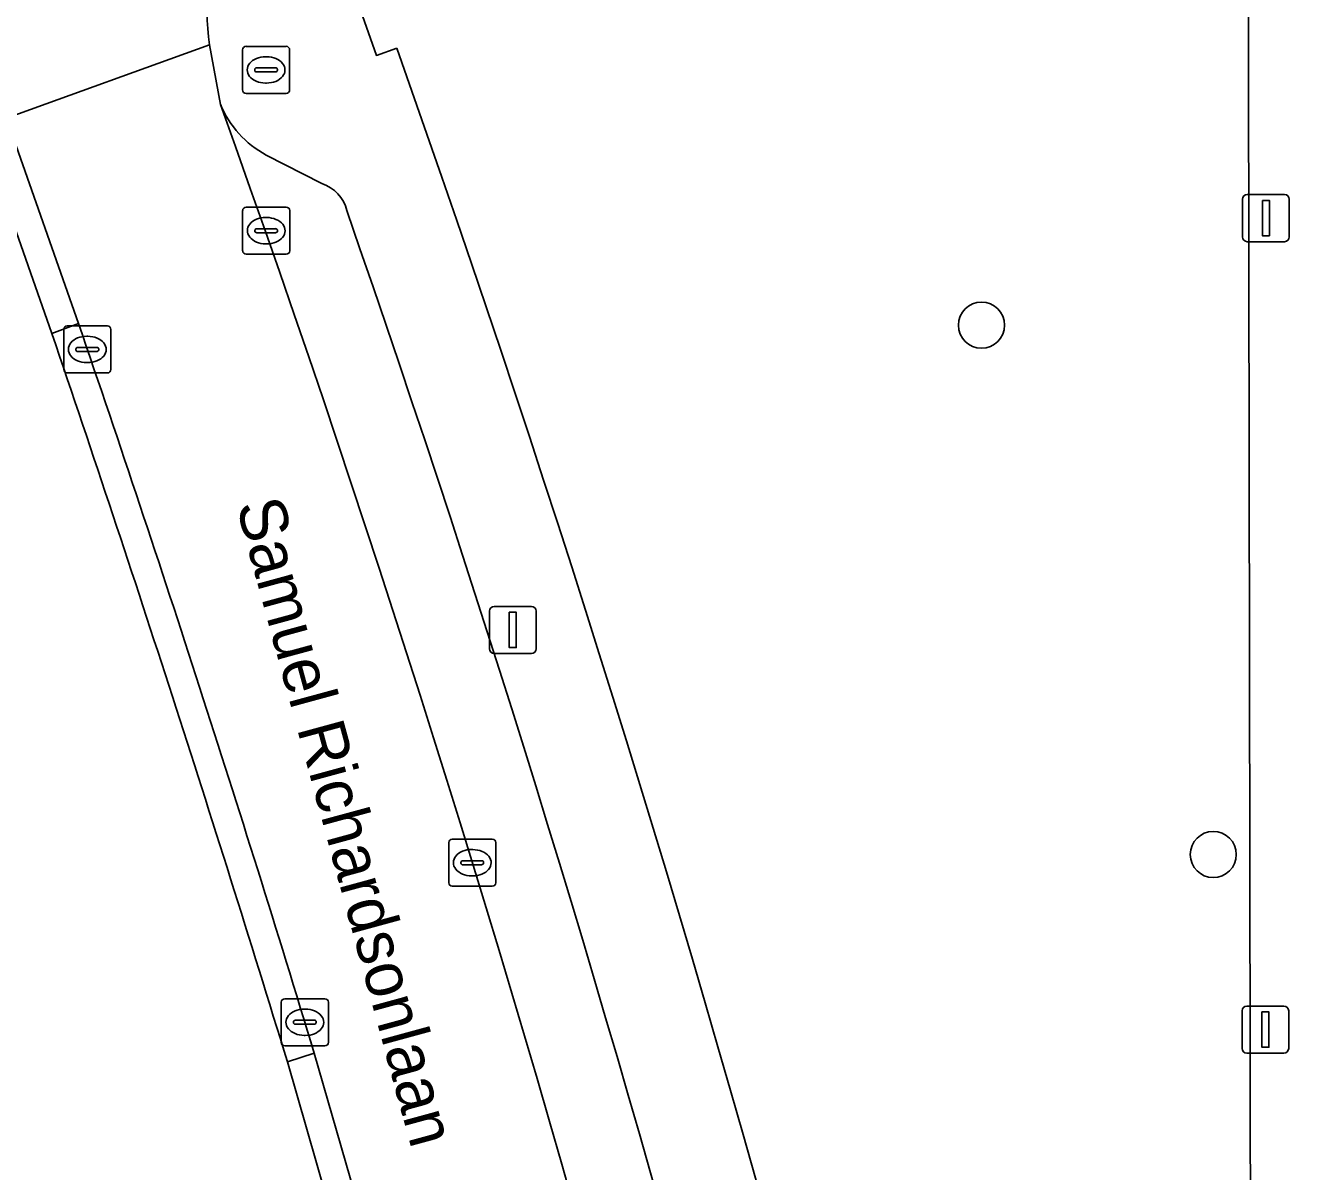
# Model space of a CAD drawing. Extents: x 160455 to 162082, y 388339 to 389736.
# Drawn here: x 160861.12 to 160888.53, y 388583.49 to 388607.82 of the extents above; entities that cross this region are included whole.
import ezdxf

# ---------------------------------------------------------------- set-up
doc = ezdxf.new("R2010")
doc.units = 0
for name, color, linetype in [('IMGEO_Boom', 7, 'Continuous'), ('IMGEO_Brandkraan', 7, 'Continuous'), ('IMGEO_Erf', 7, 'Continuous'), ('IMGEO_Groenvoorziening', 7, 'Continuous'), ('IMGEO_Kolk', 7, 'Continuous'), ('IMGEO_Lichtmast', 7, 'Continuous'), ('IMGEO_Openbare_ruimte_label', 7, 'Continuous'), ('IMGEO_Parkeervlak_open', 7, 'Continuous'), ('IMGEO_Rijbaan_lokaal_open', 7, 'Continuous'), ('IMGEO_Voetpad_open', 7, 'Continuous')]:
    doc.layers.add(name, color=color, linetype=linetype)

msp = doc.modelspace()

# ---------------------------------------------------------------- linework, layer by layer
at = {"layer": 'IMGEO_Boom'}
for centre in [(160881.421, 388601.46), (160886.345, 388590.216)]:
    msp.add_circle(centre, 0.489, dxfattribs=at)
at = {"layer": 'IMGEO_Brandkraan'}
for p, q in [((160865.722, 388606.457), (160865.722, 388607.309)), ((160865.797, 388607.383), (160866.649, 388607.383)), ((160866.723, 388607.309), (160866.723, 388606.457)), ((160866.21, 388607.163), (160866.235, 388607.163)), ((160865.981, 388606.877), (160865.981, 388606.889)), ((160866.419, 388606.84), (160866.021, 388606.84)), ((160866.024, 388606.926), (160866.422, 388606.926)), ((160866.465, 388606.889), (160866.465, 388606.877)), ((160866.233, 388606.603), (160866.208, 388606.603)), ((160866.649, 388606.383), (160865.797, 388606.383))]:
    msp.add_line(p, q, dxfattribs=at)
for points in [[(160865.722, 388606.457), (160865.722, 388607.309)], [(160865.797, 388607.383), (160866.649, 388607.383)], [(160866.723, 388607.309), (160866.723, 388606.457)], [(160866.649, 388606.383), (160865.797, 388606.383)]]:
    msp.add_lwpolyline(points, dxfattribs=at)
for centre, radius, start, end in [((160865.799, 388607.307), 0.0765, 91.552, 178.448), ((160865.799, 388607.307), 0.0765, 91.552, 178.448), ((160866.647, 388607.307), 0.0765, 1.552, 88.448), ((160866.647, 388607.307), 0.0765, 1.552, 88.448), ((160866.021, 388606.886), 0.0403, 85.8775, 175.7526), ((160866.018, 388606.876), 0.0366, 178.938, 274.7102), ((160866.422, 388606.883), 0.043, 264.8664, 352.4533), ((160866.426, 388606.888), 0.0386, 1.7309, 96.639), ((160865.799, 388606.459), 0.0765, 181.552, 268.448), ((160865.799, 388606.459), 0.0765, 181.552, 268.448), ((160866.647, 388606.459), 0.0765, 271.552, 358.448), ((160866.647, 388606.459), 0.0765, 271.552, 358.448)]:
    msp.add_arc(centre, radius, start, end, dxfattribs=at)
for centre, major_axis, ratio, start_param, end_param in [((160866.209, 388606.883), (-0.387, 0.002), 0.722429, 4.712389, 7.853982), ((160866.234, 388606.883), (-0.39, 0.002), 0.717154, 1.570796, 4.712389)]:
    msp.add_ellipse(centre, major_axis=major_axis, ratio=ratio, start_param=start_param, end_param=end_param, dxfattribs=at)
at = {"layer": 'IMGEO_Erf'}
for points in [[(160861.672, 388601.285), (160860.206, 388605.457)], [(160868.112, 388580.808), (160866.675, 388585.815)]]:
    msp.add_lwpolyline(points, dxfattribs=at)
msp.add_arc((160370.776, 388433.985), 518.621, 17.02306, 18.81937, dxfattribs=at)
at = {"layer": 'IMGEO_Groenvoorziening'}
for points in [[(160884.845, 388547.466), (160887.189, 388547.484), (160887.078, 388615.554)], [(160866.752, 388612.348), (160868.566, 388607.191), (160868.998, 388607.347)]]:
    msp.add_lwpolyline(points, dxfattribs=at)
msp.add_arc((160512.993, 388481.096), 377.728, 10.11988, 19.52619, dxfattribs=at)
at = {"layer": 'IMGEO_Kolk'}
for p, q in [((160865.725, 388603.041), (160865.725, 388603.893)), ((160865.8, 388603.967), (160866.652, 388603.967)), ((160866.213, 388603.747), (160866.238, 388603.747)), ((160866.726, 388603.893), (160866.726, 388603.041)), ((160865.984, 388603.461), (160865.984, 388603.473)), ((160866.027, 388603.51), (160866.425, 388603.51)), ((160866.468, 388603.473), (160866.468, 388603.461)), ((160866.422, 388603.424), (160866.024, 388603.424)), ((160866.236, 388603.187), (160866.211, 388603.187)), ((160866.652, 388602.967), (160865.8, 388602.967)), ((160861.924, 388600.519), (160861.924, 388601.371)), ((160861.999, 388601.445), (160862.851, 388601.445)), ((160862.925, 388601.371), (160862.925, 388600.519)), ((160862.226, 388600.988), (160862.624, 388600.988)), ((160862.412, 388601.225), (160862.437, 388601.225)), ((160862.183, 388600.939), (160862.183, 388600.951)), ((160862.621, 388600.902), (160862.223, 388600.902)), ((160862.667, 388600.951), (160862.667, 388600.939)), ((160862.851, 388600.445), (160861.999, 388600.445)), ((160862.435, 388600.665), (160862.41, 388600.665)), ((160870.102, 388589.616), (160870.102, 388590.468)), ((160870.177, 388590.542), (160871.029, 388590.542)), ((160870.59, 388590.322), (160870.615, 388590.322)), ((160871.103, 388590.468), (160871.103, 388589.616)), ((160870.361, 388590.036), (160870.361, 388590.048)), ((160870.404, 388590.085), (160870.802, 388590.085)), ((160870.845, 388590.048), (160870.845, 388590.036)), ((160870.799, 388589.999), (160870.401, 388589.999)), ((160870.613, 388589.762), (160870.588, 388589.762)), ((160871.029, 388589.542), (160870.177, 388589.542)), ((160866.545, 388586.227), (160866.545, 388587.079)), ((160866.62, 388587.153), (160867.472, 388587.153)), ((160867.546, 388587.079), (160867.546, 388586.227)), ((160867.033, 388586.933), (160867.058, 388586.933)), ((160866.804, 388586.647), (160866.804, 388586.659)), ((160867.242, 388586.61), (160866.844, 388586.61)), ((160866.847, 388586.696), (160867.245, 388586.696)), ((160867.288, 388586.659), (160867.288, 388586.647)), ((160867.056, 388586.373), (160867.031, 388586.373)), ((160867.472, 388586.153), (160866.62, 388586.153))]:
    msp.add_line(p, q, dxfattribs=at)
for points in [[(160865.725, 388603.041), (160865.725, 388603.893)], [(160865.8, 388603.967), (160866.652, 388603.967)], [(160866.726, 388603.893), (160866.726, 388603.041)], [(160866.652, 388602.967), (160865.8, 388602.967)], [(160861.924, 388600.519), (160861.924, 388601.371)], [(160861.999, 388601.445), (160862.851, 388601.445)], [(160862.925, 388601.371), (160862.925, 388600.519)], [(160862.851, 388600.445), (160861.999, 388600.445)], [(160870.102, 388589.616), (160870.102, 388590.468)], [(160870.177, 388590.542), (160871.029, 388590.542)], [(160871.103, 388590.468), (160871.103, 388589.616)], [(160871.029, 388589.542), (160870.177, 388589.542)], [(160866.545, 388586.227), (160866.545, 388587.079)], [(160866.62, 388587.153), (160867.472, 388587.153)], [(160867.546, 388587.079), (160867.546, 388586.227)], [(160867.472, 388586.153), (160866.62, 388586.153)]]:
    msp.add_lwpolyline(points, dxfattribs=at)
for centre, radius, start, end in [((160865.802, 388603.891), 0.0765, 91.552, 178.448), ((160865.802, 388603.891), 0.0765, 91.552, 178.448), ((160866.65, 388603.891), 0.0765, 1.552, 88.448), ((160866.65, 388603.891), 0.0765, 1.552, 88.448), ((160866.024, 388603.47), 0.0403, 85.8775, 175.7526), ((160866.021, 388603.46), 0.0366, 178.938, 274.7102), ((160866.425, 388603.467), 0.043, 264.8664, 352.4533), ((160866.429, 388603.472), 0.0386, 1.7309, 96.639), ((160865.802, 388603.043), 0.0765, 181.552, 268.448), ((160865.802, 388603.043), 0.0765, 181.552, 268.448), ((160866.65, 388603.043), 0.0765, 271.552, 358.448), ((160866.65, 388603.043), 0.0765, 271.552, 358.448), ((160862.001, 388601.369), 0.0765, 91.552, 178.448), ((160862.001, 388601.369), 0.0765, 91.552, 178.448), ((160862.849, 388601.369), 0.0765, 1.552, 88.448), ((160862.849, 388601.369), 0.0765, 1.552, 88.448), ((160862.223, 388600.948), 0.0403, 85.8775, 175.7526), ((160862.628, 388600.95), 0.0386, 1.7309, 96.639), ((160862.22, 388600.938), 0.0366, 178.938, 274.7102), ((160862.624, 388600.945), 0.043, 264.8664, 352.4533), ((160862.001, 388600.521), 0.0765, 181.552, 268.448), ((160862.001, 388600.521), 0.0765, 181.552, 268.448), ((160862.849, 388600.521), 0.0765, 271.552, 358.448), ((160862.849, 388600.521), 0.0765, 271.552, 358.448), ((160870.179, 388590.466), 0.0765, 91.552, 178.448), ((160870.179, 388590.466), 0.0765, 91.552, 178.448), ((160871.027, 388590.466), 0.0765, 1.552, 88.448), ((160871.027, 388590.466), 0.0765, 1.552, 88.448), ((160870.401, 388590.045), 0.0403, 85.8775, 175.7526), ((160870.398, 388590.035), 0.0366, 178.938, 274.7102), ((160870.802, 388590.042), 0.043, 264.8664, 352.4533), ((160870.806, 388590.047), 0.0386, 1.7309, 96.639), ((160870.179, 388589.618), 0.0765, 181.552, 268.448), ((160870.179, 388589.618), 0.0765, 181.552, 268.448), ((160871.027, 388589.618), 0.0765, 271.552, 358.448), ((160871.027, 388589.618), 0.0765, 271.552, 358.448), ((160866.622, 388587.077), 0.0765, 91.552, 178.448), ((160866.622, 388587.077), 0.0765, 91.552, 178.448), ((160867.47, 388587.077), 0.0765, 1.552, 88.448), ((160867.47, 388587.077), 0.0765, 1.552, 88.448), ((160866.844, 388586.656), 0.0403, 85.8775, 175.7526), ((160866.841, 388586.646), 0.0366, 178.938, 274.7102), ((160867.245, 388586.653), 0.043, 264.8664, 352.4533), ((160867.249, 388586.658), 0.0386, 1.7309, 96.639), ((160866.622, 388586.229), 0.0765, 181.552, 268.448), ((160866.622, 388586.229), 0.0765, 181.552, 268.448), ((160867.47, 388586.229), 0.0765, 271.552, 358.448), ((160867.47, 388586.229), 0.0765, 271.552, 358.448)]:
    msp.add_arc(centre, radius, start, end, dxfattribs=at)
for centre, major_axis, ratio, start_param, end_param in [((160866.212, 388603.467), (-0.387, 0.002), 0.722429, 4.712389, 7.853982), ((160866.237, 388603.467), (-0.39, 0.002), 0.717154, 1.570796, 4.712389), ((160862.411, 388600.945), (-0.387, 0.002), 0.722429, 4.712389, 7.853982), ((160862.436, 388600.945), (-0.39, 0.002), 0.717154, 1.570796, 4.712389), ((160870.589, 388590.042), (-0.387, 0.002), 0.722429, 4.712389, 7.853982), ((160870.614, 388590.042), (-0.39, 0.002), 0.717154, 1.570796, 4.712389), ((160867.032, 388586.653), (-0.387, 0.002), 0.722429, 4.712389, 7.853982), ((160867.057, 388586.653), (-0.39, 0.002), 0.717154, 1.570796, 4.712389)]:
    msp.add_ellipse(centre, major_axis=major_axis, ratio=ratio, start_param=start_param, end_param=end_param, dxfattribs=at)
at = {"layer": 'IMGEO_Lichtmast'}
for p, q in [((160886.968, 388603.334), (160886.968, 388604.134)), ((160886.968, 388604.134), (160886.968, 388603.334)), ((160887.068, 388604.234), (160887.858, 388604.234)), ((160887.858, 388604.234), (160887.068, 388604.234)), ((160887.958, 388604.134), (160887.958, 388603.334)), ((160887.958, 388603.334), (160887.958, 388604.134)), ((160887.858, 388603.234), (160887.068, 388603.234)), ((160887.068, 388603.234), (160887.858, 388603.234)), ((160870.969, 388594.587), (160870.969, 388595.387)), ((160870.969, 388595.387), (160870.969, 388594.587)), ((160871.069, 388595.487), (160871.859, 388595.487)), ((160871.859, 388595.487), (160871.069, 388595.487)), ((160871.959, 388595.387), (160871.959, 388594.587)), ((160871.959, 388594.587), (160871.959, 388595.387)), ((160871.859, 388594.487), (160871.069, 388594.487)), ((160871.069, 388594.487), (160871.859, 388594.487)), ((160887.057, 388586.998), (160887.847, 388586.998)), ((160887.847, 388586.998), (160887.057, 388586.998)), ((160886.957, 388586.098), (160886.957, 388586.898)), ((160886.957, 388586.898), (160886.957, 388586.098)), ((160887.947, 388586.898), (160887.947, 388586.098)), ((160887.947, 388586.098), (160887.947, 388586.898)), ((160887.847, 388585.998), (160887.057, 388585.998)), ((160887.057, 388585.998), (160887.847, 388585.998))]:
    msp.add_line(p, q, dxfattribs=at)
for points in [[(160887.388, 388604.109), (160887.538, 388604.109), (160887.538, 388603.359), (160887.388, 388603.359), (160887.388, 388604.109)], [(160871.389, 388595.362), (160871.539, 388595.362), (160871.539, 388594.612), (160871.389, 388594.612), (160871.389, 388595.362)], [(160887.377, 388586.873), (160887.527, 388586.873), (160887.527, 388586.123), (160887.377, 388586.123), (160887.377, 388586.873)]]:
    msp.add_lwpolyline(points, dxfattribs=at)
for centre, start, end in [((160887.068, 388604.134), 90, 180), ((160887.068, 388604.134), 90, 180), ((160887.858, 388604.134), 0, 90), ((160887.858, 388604.134), 360, 90), ((160887.068, 388603.334), 180, 270), ((160887.068, 388603.334), 180, 270), ((160887.858, 388603.334), 270, 0), ((160887.858, 388603.334), 270, 0), ((160871.069, 388595.387), 90, 180), ((160871.069, 388595.387), 90, 180), ((160871.859, 388595.387), 0, 90), ((160871.859, 388595.387), 360, 90), ((160871.069, 388594.587), 180, 270), ((160871.069, 388594.587), 180, 270), ((160871.859, 388594.587), 270, 0), ((160871.859, 388594.587), 270, 0), ((160887.057, 388586.898), 90, 180), ((160887.057, 388586.898), 90, 180), ((160887.847, 388586.898), 0, 90), ((160887.847, 388586.898), 360, 90), ((160887.057, 388586.098), 180, 270), ((160887.057, 388586.098), 180, 270), ((160887.847, 388586.098), 270, 0), ((160887.847, 388586.098), 270, 0)]:
    msp.add_arc(centre, 0.1, start, end, dxfattribs=at)
at = {"layer": 'IMGEO_Parkeervlak_open'}
msp.add_lwpolyline([(160867.407, 388604.467), (160866.226, 388605.073)], dxfattribs=at)
for centre, radius, start, end in [((160867.259, 388606.984), 2.172, 202.5412, 241.5975), ((160524.9, 388484.103), 361.574, 10.13228, 19.72738), ((160867.167, 388603.714), 0.79, 13.0861, 72.3492), ((160520.167, 388482.861), 368.229, 10.65191, 19.18911)]:
    msp.add_arc(centre, radius, start, end, dxfattribs=at)
at = {"layer": 'IMGEO_Rijbaan_lokaal_open'}
for points in [[(160865.253, 388606.151), (160865.02, 388607.416), (160860.705, 388605.854), (160860.77, 388605.674), (160862.237, 388601.497)], [(160860.705, 388605.854), (160865.02, 388607.416)], [(160867.247, 388585.996), (160868.679, 388581.017)]]:
    msp.add_lwpolyline(points, dxfattribs=at)
for centre, radius, start, end in [((160870.67, 388608.202), 5.704, 133.3791, 187.9207), ((160524.9, 388484.103), 361.574, 10.13228, 19.72738), ((160429.852, 388453.188), 457.113, 16.89009, 18.93209)]:
    msp.add_arc(centre, radius, start, end, dxfattribs=at)
at = {"layer": 'IMGEO_Voetpad_open'}
for points in [[(160892.082, 388619.048), (160887.065, 388619.167), (160887.078, 388615.554), (160887.189, 388547.484), (160890.205, 388547.5), (160890.136, 388590.2)], [(160868.998, 388607.347), (160868.566, 388607.191), (160866.752, 388612.348)], [(160865.02, 388607.416), (160865.253, 388606.151)], [(160866.226, 388605.073), (160867.407, 388604.467)], [(160862.237, 388601.497), (160861.672, 388601.285)], [(160866.675, 388585.815), (160867.247, 388585.996)]]:
    msp.add_lwpolyline(points, dxfattribs=at)
for points in [[(160860.77, 388605.674), (160860.206, 388605.457), (160861.672, 388601.285), (160862.237, 388601.497)], [(160868.679, 388581.017), (160867.247, 388585.996), (160866.675, 388585.815), (160868.112, 388580.808)]]:
    msp.add_lwpolyline(points, close=True, dxfattribs=at)
for centre, radius, start, end in [((160870.67, 388608.202), 5.704, 133.3791, 187.9207), ((160512.993, 388481.096), 377.728, 10.11988, 19.52619), ((160867.259, 388606.984), 2.172, 202.5412, 241.5975), ((160867.167, 388603.714), 0.79, 13.0861, 72.3492), ((160520.167, 388482.861), 368.229, 10.65191, 19.18911), ((160370.776, 388433.985), 518.621, 17.02306, 18.81937), ((160429.852, 388453.188), 457.113, 16.89009, 18.93209)]:
    msp.add_arc(centre, radius, start, end, dxfattribs=at)

# ---------------------------------------------------------------- texts
at = {"layer": 'IMGEO_Openbare_ruimte_label'}
msp.add_text('Samuel Richardsonlaan', height=1, rotation=285.2451, dxfattribs=at).set_placement((160865.584, 388597.638))

doc.saveas('drawing.dxf')
